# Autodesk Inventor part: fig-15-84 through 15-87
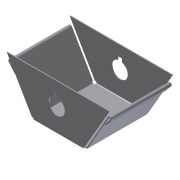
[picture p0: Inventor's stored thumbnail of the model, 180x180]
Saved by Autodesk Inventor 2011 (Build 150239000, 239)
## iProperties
Shininess: 50.0
Angle Display Precision: 2
Document Length Units: 11269
Document Angle Units: 11279
Document Time Units: 11290
Document Mass Units: 11283
Document Length Units Precision: 3
Document Angle Units Precision: 2
Created: 2002-04
Part Number: fig-15-84 through 15-87
Document SubType Name: Sheet Metal
Density: 1 g/cm^3
Sheet Metal Rule: Default
Density: 0.0
Volumn: 0.0
Area: 0.0
PropertySet Name: Model Information
Control State: 0
Master: False
Checked Out: False
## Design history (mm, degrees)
node "Face1"
  sketch "Sketch1"
    geometry: L1 (-24.824, 17.882)-(5.529, 17.882); L2 (5.529, 17.882)-(5.529, -17.529); L3 (5.529, -17.529)-(-24.824, -17.529); L4 (-24.824, -17.529)-(-24.824, 17.882)
    constraints: 8 end point, 2 parallel, 1 horizontal, 1 perpendicular
node "Flange2"
node "Flange3"
node "Flange4"
node "Flange5"
feature "Corner1" dims "d45" = 0.5 (= Thickness), "d46" = 0, "d81" = 2 (= CornerReliefSize), "Thickness" = 0.5, "TransitionRadius" = 0.5 (= BendRadius)
feature "Corner2" dims "d47" = 0.5 (= Thickness), "d48" = 0, "d82" = 2 (= CornerReliefSize), "Thickness" = 0.5, "TransitionRadius" = 0.5 (= BendRadius)
feature "Corner3" dims "d49" = 0.5 (= Thickness), "d50" = 0, "d83" = 2 (= CornerReliefSize), "Thickness" = 0.5, "TransitionRadius" = 0.5 (= BendRadius)
feature "Corner4" dims "d51" = 0.5 (= Thickness), "d52" = 0, "d84" = 2 (= CornerReliefSize), "Thickness" = 0.5, "TransitionRadius" = 0.5 (= BendRadius)
feature "Hem1" dims "d53" = 0.5 (= BendRadius), "d54" = 190 deg, "d55" = 0.5 (= BendRadius), "d56" = 0.5 (= d55), "d75" = 0.5 (= BendReliefWidth), "d76" = 0.25 (= BendReliefDepth), "d77" = 1 (= MinimumRemnant), "SeamGap" = 0.01, "Thickness" = 0.5, "MinimumRemnant" = 1 (= 2 x Thickness), "BendReliefWidth" = 0.5 (= Thickness)
feature "Hem2" dims "d57" = 0.5 (= BendRadius), "d58" = 190 deg, "d59" = 0.5 (= BendRadius), "d60" = 0.5 (= d59), "d78" = 0.5 (= BendReliefWidth), "d79" = 0.25 (= BendReliefDepth), "d80" = 1 (= MinimumRemnant), "SeamGap" = 0.01, "Thickness" = 0.5, "MinimumRemnant" = 1 (= 2 x Thickness), "BendReliefWidth" = 0.5 (= Thickness)
sketch "Sketch12"
  geometry: L1 (28.924, -7.829)-(28.924, -5.94); L2 (28.924, -5.94)-(26.464, -5.94); L3 (26.464, -5.94)-(26.464, -7.829); A1 r 4.497 centre (27.694, -12.155) between (26.464, -7.829) and (28.924, -7.829)
  constraints: 6 end point, 2 point on circle, 1 centre point, 1 parallel
cut "Cut1" sketch "Sketch12" dims "d61" = 0.5 (= Thickness), "d62" = 0
body "Solid1"
face "Plate1" dims "Thickness" = 0.5
sketch "Sketch6"
  geometry: L1 (30.412, 0)-(5, 0); L2 (5, 0)-(5, 25); L3 (5, 25)-(30.412, 25); L4 (30.412, 25)-(30.412, 0)
  constraints: 8 end point
face "Plate7" dims "d21" = 5, "d22" = 5, "d24" = 25, "d25" = 60 deg, "d26" = 0.5 (= BendRadius), "Thickness" = 0.5, "MinimumRemnant" = 1 (= 2 x Thickness), "BendReliefWidth" = 0.5 (= Thickness)
bend "Bend6" dims "d23" = 0.5 (= BendRadius), "d24" = 25, "d25" = 60 deg, "d26" = 0.5 (= BendRadius), "d63" = 0.5 (= BendReliefWidth), "d64" = 0.25 (= BendReliefDepth), "d65" = 1 (= MinimumRemnant), "SeamGap" = 0.01, "Thickness" = 0.5, "MinimumRemnant" = 1 (= 2 x Thickness), "BendReliefWidth" = 0.5 (= Thickness)
sketch "Sketch7"
  geometry: L1 (25.353, 0)-(5, 0); L2 (5, 0)-(5, 25); L3 (5, 25)-(25.353, 25); L4 (25.353, 25)-(25.353, 0)
  constraints: 8 end point
face "Plate8" dims "d27" = 5, "d28" = 5, "d30" = 25, "d31" = 90 deg, "d32" = 0.5 (= BendRadius), "Thickness" = 0.5, "MinimumRemnant" = 1 (= 2 x Thickness), "BendReliefWidth" = 0.5 (= Thickness)
bend "Bend7" dims "d29" = 0.5 (= BendRadius), "d30" = 25, "d31" = 90 deg, "d32" = 0.5 (= BendRadius), "d66" = 0.5 (= BendReliefWidth), "d67" = 0.25 (= BendReliefDepth), "d68" = 1 (= MinimumRemnant), "SeamGap" = 0.01, "Thickness" = 0.5, "MinimumRemnant" = 1 (= 2 x Thickness), "BendReliefWidth" = 0.5 (= Thickness)
sketch "Sketch8"
  geometry: L1 (5, 0)-(30.412, 0); L2 (30.412, 0)-(30.412, 25); L3 (30.412, 25)-(5, 25); L4 (5, 25)-(5, 0)
  constraints: 8 end point
face "Plate9" dims "d33" = 5, "d34" = 5, "d36" = 25, "d37" = 60 deg, "d38" = 0.5 (= BendRadius), "Thickness" = 0.5, "MinimumRemnant" = 1 (= 2 x Thickness), "BendReliefWidth" = 0.5 (= Thickness)
bend "Bend8" dims "d35" = 0.5 (= BendRadius), "d36" = 25, "d37" = 60 deg, "d38" = 0.5 (= BendRadius), "d69" = 0.5 (= BendReliefWidth), "d70" = 0.25 (= BendReliefDepth), "d71" = 1 (= MinimumRemnant), "SeamGap" = 0.01, "Thickness" = 0.5, "MinimumRemnant" = 1 (= 2 x Thickness), "BendReliefWidth" = 0.5 (= Thickness)
sketch "Sketch9"
  geometry: L1 (5, 0)-(25.353, 0); L2 (25.353, 0)-(25.353, 25); L3 (25.353, 25)-(5, 25); L4 (5, 25)-(5, 0)
  constraints: 8 end point
face "Plate10" dims "d39" = 5, "d40" = 5, "d42" = 25, "d43" = 90 deg, "d44" = 0.5 (= BendRadius), "Thickness" = 0.5, "MinimumRemnant" = 1 (= 2 x Thickness), "BendReliefWidth" = 0.5 (= Thickness)
bend "Bend9" dims "d41" = 0.5 (= BendRadius), "d42" = 25, "d43" = 90 deg, "d44" = 0.5 (= BendRadius), "d72" = 0.5 (= BendReliefWidth), "d73" = 0.25 (= BendReliefDepth), "d74" = 1 (= MinimumRemnant), "SeamGap" = 0.01, "Thickness" = 0.5, "MinimumRemnant" = 1 (= 2 x Thickness), "BendReliefWidth" = 0.5 (= Thickness)
sketch "Sketch10"
  geometry: L1 (0.433, 0.25)-(0, 0); L2 (-0.816, -0.571)-(2.395, -4.398); L3 (2.395, -4.398)-(2.012, -4.719); L4 (2.012, -4.719)-(-1.199, -0.893); A1 r 0.5 centre (-0.433, -0.25) between (0, 0) and (-0.816, -0.571); A2 r 1 centre (-0.433, -0.25) between (0.433, 0.25) and (-1.199, -0.893)
  constraints: 8 end point, 4 point on circle
sketch "Sketch11"
  geometry: L1 (0.433, 0.25)-(0, 0); L2 (-0.816, -0.571)-(2.395, -4.398); L3 (2.395, -4.398)-(2.012, -4.719); L4 (2.012, -4.719)-(-1.199, -0.893); A1 r 0.5 centre (-0.433, -0.25) between (0, 0) and (-0.816, -0.571); A2 r 1 centre (-0.433, -0.25) between (0.433, 0.25) and (-1.199, -0.893)
  constraints: 8 end point, 4 point on circle
node "FlatPattern"
feature "FlatPatternExtrusion2" dims "d0" = 0.5 (derived)
other parameters: "BendRadius" = 0.5 (= Thickness), "BendReliefDepth" = 0.25 (= 0.5 x Thickness), "CornerReliefSize" = 2 (= 4 x Thickness), "d0" = 0.5 (= BendRadius), "d4" = 0.5 (= BendRadius), "JacobiRadiusSize" = 0.5 (= Thickness), "GapSize" = 0.5 (= Thickness)
